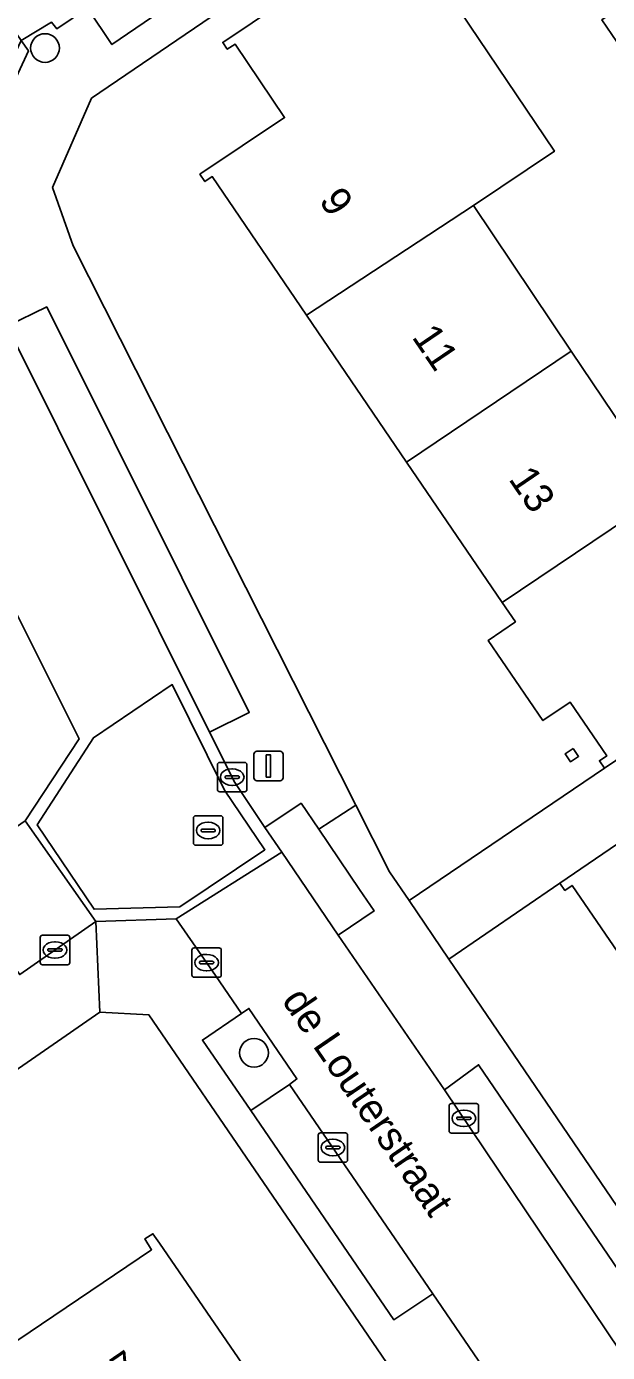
# Model space of a CAD drawing. Extents: x 157445 to 158888, y 383061 to 384688.
# Drawn here: x 158122.05 to 158141.78, y 383419.34 to 383464.42 of the extents above; entities that cross this region are included whole.
import ezdxf

# ---------------------------------------------------------------- set-up
doc = ezdxf.new("R2010")
doc.units = 0
for name, color, linetype in [('IMGEO_Boom', 7, 'Continuous'), ('IMGEO_Erf', 7, 'Continuous'), ('IMGEO_Groenvoorziening', 7, 'Continuous'), ('IMGEO_Kolk', 7, 'Continuous'), ('IMGEO_Lichtmast', 7, 'Continuous'), ('IMGEO_Openbare_ruimte_label', 7, 'Continuous'), ('IMGEO_Pand', 7, 'Continuous'), ('IMGEO_Pand_nummerreeks', 7, 'Continuous'), ('IMGEO_Parkeervlak_open', 7, 'Continuous'), ('IMGEO_Rijbaan_lokaal_open', 7, 'Continuous'), ('IMGEO_Rioolput', 7, 'Continuous'), ('IMGEO_Voetpad_open', 7, 'Continuous')]:
    doc.layers.add(name, color=color, linetype=linetype)

msp = doc.modelspace()

# ---------------------------------------------------------------- linework, layer by layer
at = {"layer": 'IMGEO_Boom'}
for centre in [(158122.674, 383463.684), (158129.774, 383429.53)]:
    msp.add_circle(centre, 0.489, dxfattribs=at)
at = {"layer": 'IMGEO_Erf'}
for points in [[(158139.941, 383472.663), (158124.256, 383461.978), (158122.93, 383458.939), (158123.627, 383456.958), (158133.23, 383437.953), (158134.378, 383435.682), (158135.037, 383434.712), (158141.673, 383439.208), (158141.504, 383439.456), (158141.752, 383439.624), (158140.509, 383441.451), (158139.584, 383440.821), (158137.727, 383443.55), (158138.652, 383444.18), (158138.207, 383444.833), (158134.956, 383449.611), (158131.56, 383454.6), (158128.353, 383459.313), (158128.105, 383459.145), (158127.937, 383459.394), (158130.809, 383461.323), (158129.131, 383463.822), (158128.866, 383463.643), (158128.71, 383463.876), (158134.728, 383467.918)], [(158136.769, 383464.951), (158139.974, 383460.178), (158137.226, 383458.331), (158140.55, 383453.383), (158143.772, 383448.586), (158147.251, 383443.408), (158147.557, 383443.614), (158147.751, 383443.325), (158143.984, 383440.774), (158144.252, 383440.377), (158156.256, 383448.523), (158154.095, 383451.707), (158151.499, 383449.946), (158149.706, 383452.588), (158148.178, 383454.839), (158150.774, 383456.601), (158147.507, 383461.514), (158144.911, 383459.753), (158143.118, 383462.395), (158141.59, 383464.646)], [(158138.593, 383412.664), (158132.879, 383421.037), (158129.946, 383425.336), (158126.204, 383430.819), (158124.53, 383430.909), (158110.929, 383421.479), (158069.427, 383393.097)], [(158120.558, 383419.33), (158120.73, 383419.448), (158120.899, 383419.2), (158126.293, 383422.837), (158126.061, 383423.203), (158126.339, 383423.378), (158126.561, 383423.054), (158129.502, 383418.76)]]:
    msp.add_lwpolyline(points, dxfattribs=at)
for points in [[(158140.613, 383439.877), (158140.799, 383439.604), (158140.526, 383439.419), (158140.34, 383439.692)], [(158154.298, 383415.194), (158150.669, 383420.492), (158147.398, 383425.266), (158143.953, 383430.293), (158140.579, 383435.218), (158140.332, 383435.049), (158140.163, 383435.297), (158136.393, 383432.718), (158156.85, 383402.629), (158158.091, 383403.465), (158160.724, 383405.287), (158160.554, 383405.534), (158160.801, 383405.703), (158157.635, 383410.324)]]:
    msp.add_lwpolyline(points, close=True, dxfattribs=at)
at = {"layer": 'IMGEO_Groenvoorziening'}
msp.add_lwpolyline([(158130.981, 383428.451), (158131.231, 383428.643), (158129.597, 383431.041), (158129.35, 383430.87), (158128.021, 383429.963), (158129.67, 383427.57)], close=True, dxfattribs=at)
at = {"layer": 'IMGEO_Kolk'}
for p, q in [((158128.606, 383439.401), (158129.458, 383439.401)), ((158128.531, 383438.475), (158128.531, 383439.327)), ((158128.79, 383438.895), (158128.79, 383438.907)), ((158128.833, 383438.944), (158129.231, 383438.944)), ((158129.019, 383439.181), (158129.044, 383439.181)), ((158129.274, 383438.907), (158129.274, 383438.895)), ((158129.532, 383439.327), (158129.532, 383438.475)), ((158129.228, 383438.858), (158128.83, 383438.858)), ((158129.042, 383438.621), (158129.017, 383438.621)), ((158129.458, 383438.401), (158128.606, 383438.401)), ((158122.587, 383433.525), (158123.439, 383433.525)), ((158122.512, 383432.599), (158122.512, 383433.451)), ((158122.814, 383433.068), (158123.212, 383433.068)), ((158123, 383433.305), (158123.025, 383433.305)), ((158123.513, 383433.451), (158123.513, 383432.599)), ((158127.736, 383433.096), (158128.588, 383433.096)), ((158122.771, 383433.019), (158122.771, 383433.031)), ((158123.209, 383432.982), (158122.811, 383432.982)), ((158123.023, 383432.745), (158122.998, 383432.745)), ((158123.255, 383433.031), (158123.255, 383433.019)), ((158127.661, 383432.17), (158127.661, 383433.022)), ((158127.92, 383432.59), (158127.92, 383432.602)), ((158127.963, 383432.639), (158128.361, 383432.639)), ((158128.149, 383432.876), (158128.174, 383432.876)), ((158128.404, 383432.602), (158128.404, 383432.59)), ((158128.662, 383433.022), (158128.662, 383432.17)), ((158123.439, 383432.525), (158122.587, 383432.525)), ((158128.358, 383432.553), (158127.96, 383432.553)), ((158128.172, 383432.316), (158128.147, 383432.316)), ((158128.588, 383432.096), (158127.736, 383432.096)), ((158136.4, 383426.877), (158136.4, 383427.729)), ((158136.475, 383427.803), (158137.327, 383427.803)), ((158137.401, 383427.729), (158137.401, 383426.877)), ((158136.659, 383427.297), (158136.659, 383427.309)), ((158137.097, 383427.26), (158136.699, 383427.26)), ((158136.702, 383427.346), (158137.1, 383427.346)), ((158136.888, 383427.583), (158136.913, 383427.583)), ((158137.143, 383427.309), (158137.143, 383427.297)), ((158131.951, 383425.883), (158131.951, 383426.735)), ((158132.026, 383426.809), (158132.878, 383426.809)), ((158132.952, 383426.735), (158132.952, 383425.883)), ((158137.327, 383426.803), (158136.475, 383426.803)), ((158136.911, 383427.023), (158136.886, 383427.023)), ((158132.21, 383426.303), (158132.21, 383426.315)), ((158132.253, 383426.352), (158132.651, 383426.352)), ((158132.439, 383426.589), (158132.464, 383426.589)), ((158132.694, 383426.315), (158132.694, 383426.303)), ((158132.648, 383426.266), (158132.25, 383426.266)), ((158132.462, 383426.029), (158132.437, 383426.029)), ((158132.878, 383425.809), (158132.026, 383425.809))]:
    msp.add_line(p, q, dxfattribs=at)
for points in [[(158128.606, 383439.401), (158129.458, 383439.401)], [(158128.531, 383438.475), (158128.531, 383439.327)], [(158129.532, 383439.327), (158129.532, 383438.475)], [(158129.458, 383438.401), (158128.606, 383438.401)], [(158122.587, 383433.525), (158123.439, 383433.525)], [(158122.512, 383432.599), (158122.512, 383433.451)], [(158123.513, 383433.451), (158123.513, 383432.599)], [(158127.736, 383433.096), (158128.588, 383433.096)], [(158127.661, 383432.17), (158127.661, 383433.022)], [(158128.662, 383433.022), (158128.662, 383432.17)], [(158123.439, 383432.525), (158122.587, 383432.525)], [(158128.588, 383432.096), (158127.736, 383432.096)], [(158136.4, 383426.877), (158136.4, 383427.729)], [(158136.475, 383427.803), (158137.327, 383427.803)], [(158137.401, 383427.729), (158137.401, 383426.877)], [(158131.951, 383425.883), (158131.951, 383426.735)], [(158132.026, 383426.809), (158132.878, 383426.809)], [(158132.952, 383426.735), (158132.952, 383425.883)], [(158137.327, 383426.803), (158136.475, 383426.803)], [(158132.878, 383425.809), (158132.026, 383425.809)]]:
    msp.add_lwpolyline(points, dxfattribs=at)
for centre, radius, start, end in [((158128.608, 383439.325), 0.0765, 91.552, 178.448), ((158128.608, 383439.325), 0.0765, 91.552, 178.448), ((158129.456, 383439.325), 0.0765, 1.552, 88.448), ((158129.456, 383439.325), 0.0765, 1.552, 88.448), ((158128.83, 383438.904), 0.0403, 85.8775, 175.7526), ((158129.235, 383438.906), 0.0386, 1.7309, 96.639), ((158128.608, 383438.477), 0.0765, 181.552, 268.448), ((158128.608, 383438.477), 0.0765, 181.552, 268.448), ((158128.827, 383438.894), 0.0366, 178.938, 274.7102), ((158129.231, 383438.901), 0.043, 264.8664, 352.4533), ((158129.456, 383438.477), 0.0765, 271.552, 358.448), ((158129.456, 383438.477), 0.0765, 271.552, 358.448), ((158122.589, 383433.449), 0.0765, 91.552, 178.448), ((158122.589, 383433.449), 0.0765, 91.552, 178.448), ((158123.437, 383433.449), 0.0765, 1.552, 88.448), ((158123.437, 383433.449), 0.0765, 1.552, 88.448), ((158122.811, 383433.028), 0.0403, 85.8775, 175.7526), ((158123.216, 383433.03), 0.0386, 1.7309, 96.639), ((158127.738, 383433.02), 0.0765, 91.552, 178.448), ((158127.738, 383433.02), 0.0765, 91.552, 178.448), ((158128.586, 383433.02), 0.0765, 1.552, 88.448), ((158128.586, 383433.02), 0.0765, 1.552, 88.448), ((158122.589, 383432.601), 0.0765, 181.552, 268.448), ((158122.589, 383432.601), 0.0765, 181.552, 268.448), ((158122.808, 383433.018), 0.0366, 178.938, 274.7102), ((158123.212, 383433.025), 0.043, 264.8664, 352.4533), ((158123.437, 383432.601), 0.0765, 271.552, 358.448), ((158123.437, 383432.601), 0.0765, 271.552, 358.448), ((158127.96, 383432.599), 0.0403, 85.8775, 175.7526), ((158128.365, 383432.601), 0.0386, 1.7309, 96.639), ((158127.738, 383432.172), 0.0765, 181.552, 268.448), ((158127.738, 383432.172), 0.0765, 181.552, 268.448), ((158127.957, 383432.589), 0.0366, 178.938, 274.7102), ((158128.361, 383432.596), 0.043, 264.8664, 352.4533), ((158128.586, 383432.172), 0.0765, 271.552, 358.448), ((158128.586, 383432.172), 0.0765, 271.552, 358.448), ((158136.477, 383427.727), 0.0765, 91.552, 178.448), ((158136.477, 383427.727), 0.0765, 91.552, 178.448), ((158137.325, 383427.727), 0.0765, 1.552, 88.448), ((158137.325, 383427.727), 0.0765, 1.552, 88.448), ((158136.699, 383427.306), 0.0403, 85.8775, 175.7526), ((158136.696, 383427.296), 0.0366, 178.938, 274.7102), ((158137.1, 383427.303), 0.043, 264.8664, 352.4533), ((158137.104, 383427.308), 0.0386, 1.7309, 96.639), ((158132.028, 383426.733), 0.0765, 91.552, 178.448), ((158132.028, 383426.733), 0.0765, 91.552, 178.448), ((158132.876, 383426.733), 0.0765, 1.552, 88.448), ((158132.876, 383426.733), 0.0765, 1.552, 88.448), ((158136.477, 383426.879), 0.0765, 181.552, 268.448), ((158136.477, 383426.879), 0.0765, 181.552, 268.448), ((158137.325, 383426.879), 0.0765, 271.552, 358.448), ((158137.325, 383426.879), 0.0765, 271.552, 358.448), ((158132.25, 383426.312), 0.0403, 85.8775, 175.7526), ((158132.247, 383426.302), 0.0366, 178.938, 274.7102), ((158132.651, 383426.309), 0.043, 264.8664, 352.4533), ((158132.655, 383426.314), 0.0386, 1.7309, 96.639), ((158132.028, 383425.885), 0.0765, 181.552, 268.448), ((158132.028, 383425.885), 0.0765, 181.552, 268.448), ((158132.876, 383425.885), 0.0765, 271.552, 358.448), ((158132.876, 383425.885), 0.0765, 271.552, 358.448)]:
    msp.add_arc(centre, radius, start, end, dxfattribs=at)
for centre, major_axis, ratio, start_param, end_param in [((158129.018, 383438.901), (-0.387, 0.002), 0.722429, 4.712389, 7.853982), ((158129.043, 383438.901), (-0.39, 0.002), 0.717154, 1.570796, 4.712389), ((158122.999, 383433.025), (-0.387, 0.002), 0.722429, 4.712389, 7.853982), ((158123.024, 383433.025), (-0.39, 0.002), 0.717154, 1.570796, 4.712389), ((158128.148, 383432.596), (-0.387, 0.002), 0.722429, 4.712389, 7.853982), ((158128.173, 383432.596), (-0.39, 0.002), 0.717154, 1.570796, 4.712389), ((158136.887, 383427.303), (-0.387, 0.002), 0.722429, 4.712389, 7.853982), ((158136.912, 383427.303), (-0.39, 0.002), 0.717154, 1.570796, 4.712389), ((158132.438, 383426.309), (-0.387, 0.002), 0.722429, 4.712389, 7.853982), ((158132.463, 383426.309), (-0.39, 0.002), 0.717154, 1.570796, 4.712389)]:
    msp.add_ellipse(centre, major_axis=major_axis, ratio=ratio, start_param=start_param, end_param=end_param, dxfattribs=at)
at = {"layer": 'IMGEO_Lichtmast'}
for p, q in [((158129.768, 383438.878), (158129.768, 383439.678)), ((158129.768, 383439.678), (158129.768, 383438.878)), ((158129.868, 383439.778), (158130.658, 383439.778)), ((158130.658, 383439.778), (158129.868, 383439.778)), ((158130.758, 383439.678), (158130.758, 383438.878)), ((158130.758, 383438.878), (158130.758, 383439.678)), ((158130.658, 383438.778), (158129.868, 383438.778)), ((158129.868, 383438.778), (158130.658, 383438.778))]:
    msp.add_line(p, q, dxfattribs=at)
msp.add_lwpolyline([(158130.188, 383439.653), (158130.338, 383439.653), (158130.338, 383438.903), (158130.188, 383438.903), (158130.188, 383439.653)], dxfattribs=at)
for centre, start, end in [((158129.868, 383439.678), 90, 180), ((158129.868, 383439.678), 90, 180), ((158130.658, 383439.678), 0, 90), ((158130.658, 383439.678), 360, 90), ((158129.868, 383438.878), 180, 270), ((158129.868, 383438.878), 180, 270), ((158130.658, 383438.878), 270, 0), ((158130.658, 383438.878), 270, 0)]:
    msp.add_arc(centre, 0.1, start, end, dxfattribs=at)
at = {"layer": 'IMGEO_Pand'}
for points in [[(158131.56, 383454.6), (158137.226, 383458.331), (158139.974, 383460.178), (158136.769, 383464.951), (158137.051, 383465.141), (158136.884, 383465.39), (158136.302, 383465), (158134.63, 383467.49), (158134.896, 383467.669), (158134.728, 383467.918), (158128.71, 383463.876), (158128.866, 383463.643), (158129.131, 383463.822), (158130.809, 383461.323), (158127.937, 383459.394), (158128.105, 383459.145), (158128.353, 383459.313)], [(158143.118, 383462.395), (158145.719, 383464.149), (158144.186, 383466.408), (158141.59, 383464.646)], [(158131.56, 383454.6), (158134.956, 383449.611), (158140.55, 383453.383), (158137.226, 383458.331)], [(158138.207, 383444.833), (158143.772, 383448.586), (158140.55, 383453.383), (158134.956, 383449.611)], [(158147.751, 383443.325), (158147.557, 383443.614), (158147.251, 383443.408), (158143.772, 383448.586), (158138.207, 383444.833), (158138.652, 383444.18), (158137.727, 383443.55), (158139.584, 383440.821), (158140.509, 383441.451), (158141.752, 383439.624), (158141.504, 383439.456), (158141.673, 383439.208), (158143.984, 383440.774)], [(158152.406, 383436.142), (158148.952, 383441.189), (158146.221, 383439.442), (158144.29, 383438.121), (158140.163, 383435.297), (158140.332, 383435.049), (158140.579, 383435.218), (158143.953, 383430.293)], [(158140.613, 383439.877), (158140.34, 383439.692), (158140.526, 383439.419), (158140.799, 383439.604)], [(158129.502, 383418.76), (158126.561, 383423.054), (158126.339, 383423.378), (158126.061, 383423.203), (158126.293, 383422.837), (158120.899, 383419.2), (158120.73, 383419.448), (158120.558, 383419.33), (158125.736, 383411.833), (158125.931, 383411.551), (158127.598, 383412.693), (158128.086, 383413.027), (158129.182, 383412.806), (158130.881, 383413.97), (158131.088, 383415.082), (158131.723, 383415.517)]]:
    msp.add_lwpolyline(points, close=True, dxfattribs=at)
at = {"layer": 'IMGEO_Parkeervlak_open'}
for points in [[(158137.192, 383473.942), (158137.023, 383473.827), (158124.112, 383465.036), (158124.945, 383463.8), (158138.023, 383472.718)], [(158121.392, 383454.232), (158128.266, 383440.429), (158129.609, 383441.098), (158122.732, 383454.885)], [(158131.969, 383437.132), (158131.371, 383438.015), (158130.144, 383437.193), (158130.716, 383436.348), (158132.627, 383433.528), (158133.851, 383434.353), (158133.361, 383435.077)], [(158136.245, 383428.269), (158149.548, 383408.46), (158150.604, 383406.887), (158150.963, 383406.353), (158152.252, 383404.434), (158153.46, 383402.634), (158154.82, 383403.529), (158137.403, 383429.123)], [(158130.981, 383428.451), (158129.67, 383427.57), (158134.523, 383420.449), (158135.849, 383421.333)]]:
    msp.add_lwpolyline(points, close=True, dxfattribs=at)
at = {"layer": 'IMGEO_Rijbaan_lokaal_open'}
for points in [[(158123.804, 383469.901), (158114.04, 383463.232), (158114.194, 383462.968), (158119.88, 383466.839), (158121.867, 383463.945), (158122.898, 383464.563), (158123.074, 383464.34), (158124.112, 383465.036), (158137.023, 383473.827), (158134.618, 383477.314)], [(158121.392, 383454.232), (158119.508, 383457.981), (158122.112, 383463.587), (158121.867, 383463.945), (158119.026, 383457.915), (158116.348, 383456.092), (158113.229, 383462.305), (158112.891, 383462.073), (158123.828, 383440.202), (158122.002, 383437.42), (158124.405, 383433.994), (158127.129, 383434.088), (158130.716, 383436.348), (158130.144, 383437.193), (158129.125, 383438.717), (158128.266, 383440.429)], [(158124.342, 383434.407), (158127.258, 383434.495), (158130.142, 383436.434), (158128.774, 383438.458), (158126.997, 383442.045), (158124.323, 383440.242), (158122.408, 383437.283)], [(158126.997, 383442.045), (158128.774, 383438.458), (158130.142, 383436.434), (158127.258, 383434.495), (158124.342, 383434.407), (158122.408, 383437.283), (158124.323, 383440.242)], [(158132.627, 383433.528), (158130.716, 383436.348), (158127.129, 383434.088), (158128.459, 383432.161), (158129.35, 383430.87), (158129.597, 383431.041), (158131.231, 383428.643), (158130.981, 383428.451), (158135.849, 383421.333), (158146.179, 383406.198), (158149.548, 383408.46), (158136.245, 383428.269)]]:
    msp.add_lwpolyline(points, close=True, dxfattribs=at)
msp.add_lwpolyline([(158121.817, 383432.191), (158124.405, 383433.994), (158122.002, 383437.42)], dxfattribs=at)
at = {"layer": 'IMGEO_Rioolput'}
for p, q in [((158127.79, 383437.587), (158128.642, 383437.587)), ((158127.715, 383436.661), (158127.715, 383437.513)), ((158128.017, 383437.13), (158128.415, 383437.13)), ((158128.203, 383437.367), (158128.228, 383437.367)), ((158128.716, 383437.513), (158128.716, 383436.661)), ((158127.974, 383437.081), (158127.974, 383437.093)), ((158128.412, 383437.044), (158128.014, 383437.044)), ((158128.226, 383436.807), (158128.201, 383436.807)), ((158128.458, 383437.093), (158128.458, 383437.081)), ((158128.642, 383436.587), (158127.79, 383436.587))]:
    msp.add_line(p, q, dxfattribs=at)
for points in [[(158127.79, 383437.587), (158128.642, 383437.587)], [(158127.715, 383436.661), (158127.715, 383437.513)], [(158128.716, 383437.513), (158128.716, 383436.661)], [(158128.642, 383436.587), (158127.79, 383436.587)]]:
    msp.add_lwpolyline(points, dxfattribs=at)
for centre, radius, start, end in [((158127.792, 383437.511), 0.0765, 91.552, 178.448), ((158127.792, 383437.511), 0.0765, 91.552, 178.448), ((158128.64, 383437.511), 0.0765, 1.552, 88.448), ((158128.64, 383437.511), 0.0765, 1.552, 88.448), ((158128.014, 383437.09), 0.0403, 85.8775, 175.7526), ((158128.419, 383437.092), 0.0386, 1.7309, 96.639), ((158127.792, 383436.663), 0.0765, 181.552, 268.448), ((158127.792, 383436.663), 0.0765, 181.552, 268.448), ((158128.011, 383437.08), 0.0366, 178.938, 274.7102), ((158128.415, 383437.087), 0.043, 264.8664, 352.4533), ((158128.64, 383436.663), 0.0765, 271.552, 358.448), ((158128.64, 383436.663), 0.0765, 271.552, 358.448)]:
    msp.add_arc(centre, radius, start, end, dxfattribs=at)
for centre, major_axis, ratio, start_param, end_param in [((158128.202, 383437.087), (-0.387, 0.002), 0.722429, 4.712389, 7.853982), ((158128.227, 383437.087), (-0.39, 0.002), 0.717154, 1.570796, 4.712389)]:
    msp.add_ellipse(centre, major_axis=major_axis, ratio=ratio, start_param=start_param, end_param=end_param, dxfattribs=at)
at = {"layer": 'IMGEO_Voetpad_open'}
for points in [[(158138.023, 383472.718), (158124.945, 383463.8), (158124.112, 383465.036), (158123.074, 383464.34), (158122.898, 383464.563), (158121.867, 383463.945), (158122.112, 383463.587), (158119.508, 383457.981), (158121.392, 383454.232), (158122.732, 383454.885), (158129.609, 383441.098), (158128.266, 383440.429), (158129.125, 383438.717), (158130.144, 383437.193), (158131.371, 383438.015), (158131.969, 383437.132), (158133.23, 383437.953), (158123.627, 383456.958), (158122.93, 383458.939), (158124.256, 383461.978), (158139.941, 383472.663)], [(158144.186, 383466.408), (158145.719, 383464.149), (158147.507, 383461.514), (158150.774, 383456.601), (158152.307, 383454.342), (158154.095, 383451.707), (158156.256, 383448.523), (158144.252, 383440.377), (158143.984, 383440.774), (158141.673, 383439.208), (158135.037, 383434.712), (158136.393, 383432.718), (158140.163, 383435.297), (158144.29, 383438.121), (158146.221, 383439.442), (158148.952, 383441.189), (158155.371, 383445.461), (158158.536, 383447.706), (158161.848, 383443.037), (158167.851, 383435.129), (158169.093, 383433.239), (158172.618, 383427.87)], [(158117.029, 383437.184), (158115.699, 383436.292), (158116.347, 383435.345), (158117.176, 383434.135), (158118.037, 383434.718), (158118.218, 383434.474), (158119.229, 383435.156), (158119.077, 383435.403), (158122.002, 383437.42), (158123.828, 383440.202), (158112.891, 383462.073)], [(158136.393, 383432.718), (158135.037, 383434.712), (158134.378, 383435.682), (158133.23, 383437.953), (158131.969, 383437.132), (158133.361, 383435.077), (158133.851, 383434.353), (158132.627, 383433.528), (158136.245, 383428.269), (158137.403, 383429.123), (158154.82, 383403.529), (158153.46, 383402.634), (158158.734, 383394.78), (158159.94, 383395.596), (158162.427, 383391.942), (158161.226, 383391.137), (158163.68, 383387.461), (158170.893, 383376.918), (158172.202, 383374.989), (158177.512, 383378.536), (158178.3, 383379.129)], [(158069.427, 383393.097), (158110.929, 383421.479), (158124.53, 383430.909), (158124.405, 383433.994), (158121.817, 383432.191), (158121.639, 383432.43), (158120.637, 383431.758), (158120.789, 383431.512), (158119.949, 383430.912), (158120.805, 383429.687), (158117.136, 383427.203), (158116.304, 383428.398), (158114.401, 383427.081), (158115.233, 383425.874), (158111.588, 383423.375), (158110.756, 383424.594), (158108.868, 383423.27), (158109.692, 383422.05), (158071.149, 383395.654)], [(158146.179, 383406.198), (158135.849, 383421.333), (158134.523, 383420.449), (158129.67, 383427.57), (158128.021, 383429.963), (158129.35, 383430.87), (158128.459, 383432.161), (158127.129, 383434.088), (158124.405, 383433.994), (158124.53, 383430.909), (158126.204, 383430.819), (158129.946, 383425.336), (158132.879, 383421.037), (158138.593, 383412.664)], [(158174.039, 383380.269), (158170.631, 383385.084), (158158.917, 383402.255), (158158.091, 383403.465), (158156.85, 383402.629), (158136.393, 383432.718)]]:
    msp.add_lwpolyline(points, dxfattribs=at)

# ---------------------------------------------------------------- texts
at = {"layer": 'IMGEO_Openbare_ruimte_label'}
msp.add_text('de Louterstraat', height=1, rotation=304.4052, dxfattribs=at).set_placement((158130.693, 383431.307))
at = {"layer": 'IMGEO_Pand_nummerreeks'}
for s, rotation, p in [('9', 304.2365, (158131.956, 383458.497)), ('11', 304.2365, (158135.111, 383453.861)), ('13', 304.2365, (158138.397, 383449.033)), ('17', 34.2973, (158124.741, 383417.808))]:
    msp.add_text(s, height=1, rotation=rotation, dxfattribs=at).set_placement(p)

doc.saveas('drawing.dxf')
